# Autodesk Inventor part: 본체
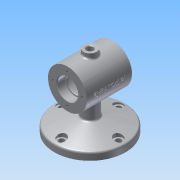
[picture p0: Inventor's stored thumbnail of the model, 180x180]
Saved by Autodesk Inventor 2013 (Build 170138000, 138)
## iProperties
Created: 2018-12
Part Number: 본체
Material: 알루미늄 6061
Document SubType Name: Modeling
Designer: Administrator
Density: 2.71 g/cm^3
Mass: 687.627 g
Surface Area: 555.481 cm^2
Volume: 253.737 cm^3
Author: Administrator
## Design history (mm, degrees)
sketch "스케치1"
  geometry: L1 (-35, 16)-(-35, 30); L2 (-35, 30)-(35, 30); L3 (35, 30)-(35, 16); L4 (35, 16)-(23, 16); L5 (23, 16)-(23, 14); L6 (23, 14)-(20, 14); L7 (20, 14)-(20, 25); L8 (20, 25)-(-20, 25); L9 (-20, 25)-(-20, 14); L10 (-20, 14)-(-23, 14); L11 (-23, 14)-(-23, 16); L12 (-23, 16)-(-35, 16); L13 (-35, 0)-(35, 0); 4 further points
  constraints: 26 end point, 11 parallel, 3 midpoint, 2 collinear, 2 point on line, 2 vertical alignment, 1 coincident, 1 perpendicular, 1 vertical
  dimensions: "d0" = 28 diameter of L10 L13; "d2" = 32 diameter of L12 L13; "d3" = 60 diameter of L2 L13; "d4" = 50 diameter of L8 L13; "d5" = 70 distance of L1.end L2.end; "d6" = 12 distance of L11.end L1.start; "d7" = 12 distance of L3.end L4.end; "d9" = 40 distance of L7.end L8.end
revolve "회전1" sketch "스케치1" stored, may be unused: angle "d10" = 90 deg
node "작업 평면1"
sketch "스케치2"
  geometry: C1 r 55 at (0, 0); 1 further point
  constraints: 1 centre point, 1 coincident
  dimensions: "d12" = 110 diameter of C1
extrude "돌출1" join sketch "스케치2" distance "d13" = 11; taper "d14" = 0 deg
sketch "스케치3"
  geometry: C1 r 55 at (0, 0); 1 further point
  constraints: 1 centre point, 1 coincident
  dimensions: "d15" = 110 diameter of C1
extrude "돌출2" join sketch "스케치3" distance "d16" = 15; taper "d17" = -75 deg
sketch "스케치4"
  geometry: C1 r 12 at (0, 0); 1 further point
  constraints: 1 centre point, 1 coincident
  dimensions: "d18" = 24 diameter of C1
extrude "돌출3" join sketch "스케치4" stored distance "d19" = 0; taper "d20" = 0 deg
sketch "스케치5"
  geometry: 2 further points
  constraints: 1 vertical alignment
  dimensions: "d21" = 23 distance of point (0, 23) point (0, 0)
hole "구멍1" sketch "스케치5" at (0, 23) diameter "d22" = 3.242; stored, may be unused: countersink angle "d26" = 90 deg, drill point angle "d28" = 118 deg; dims "d23" = 8, "d24" = 4, "d25" = 2, "d27" = 10
node "작업 평면2"
sketch "스케치6"
  geometry: C1 r 10 at (0, 0); 1 further point
  constraints: 1 centre point, 1 coincident
  dimensions: "d33" = 20 diameter of C1
extrude "돌출4" join sketch "스케치6" stored distance "d34" = 15; taper "d35" = 0 deg
hole "구멍2" diameter "d38" = 10; stored, may be unused: countersink angle "d42" = 90 deg, drill point angle "d44" = 0 deg; dims "d36" = 10, "d37" = 10, "d39" = 8, "d40" = 4, "d41" = 2, "d43" = 10
sketch "스케치7"
  geometry: 2 further points
  constraints: 1 vertical alignment
  dimensions: "d45" = 44 distance of point (0, -44) point (0, 0)
hole "구멍3" sketch "스케치7" at (0, -44) diameter "d46" = 9; stored, may be unused: countersink angle "d50" = 90 deg, drill point angle "d52" = 0 deg; dims "d47" = 8, "d48" = 4, "d49" = 2, "d51" = 10
hole "구멍4" diameter "d55" = 14; stored, may be unused: countersink angle "d59" = 90 deg, drill point angle "d61" = 0 deg; dims "d53" = 10, "d54" = 10, "d56" = 8, "d57" = 4, "d58" = 2, "d60" = 10
node "작업 평면3"
sketch "스케치8"
  geometry: L1 (-35, -30)-(-35, 30) reference; 2 further points
  constraints: 1 other
  dimensions: "d66" = 35 distance from line of L1 point (0, 0); "d67" = 30 vertical distance of L1.end point (0, 0)
feature "엠보싱1" sketch "스케치8" dims "d0" = 28, "d2" = 32, "d3" = 60, "d4" = 50, "d5" = 70, "d6" = 12, "d7" = 12, "d9" = 40, "d68" = 0.5, "d69" = 0
fillet "모깎기1" dims "d70" = 3
fillet "모깎기2" dims "d71" = 0.3
chamfer "모따기1" distance "d72" = 1; stored, may be unused: second distance "d73" = 2, angle "d74" = 45 deg
node "솔리드1"
pattern_circular "원형 패턴1" dims angle "d30" = 360 deg
mirror "대칭1"
pattern_circular "원형 패턴2" dims angle "d63" = 360 deg
other parameters: "d11" = -75, "d32" = -112, "d65" = 173.25
